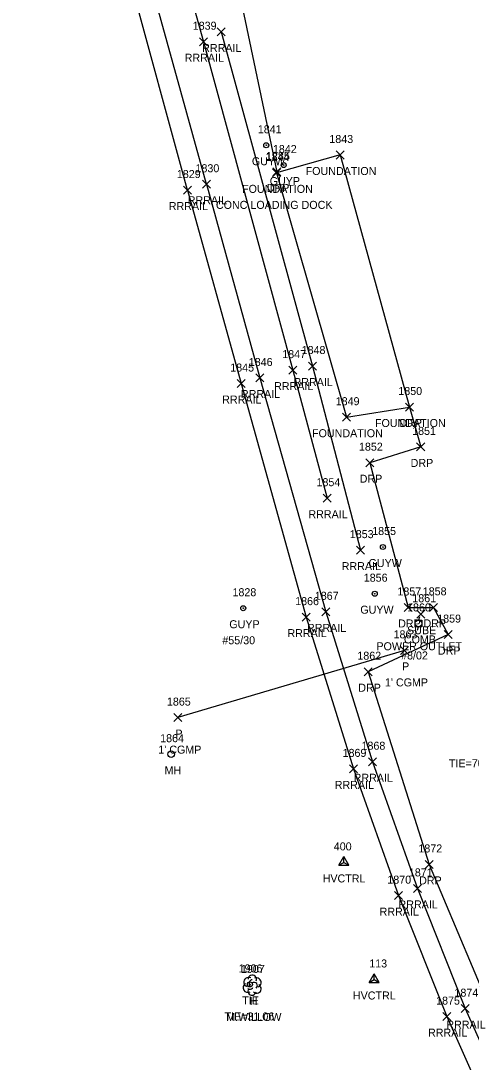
# Model space of a CAD drawing. Extents: x 1635588 to 1637550, y 621583 to 623638.
# Drawn here: x 1636548.9 to 1636661.5, y 622425.2 to 622685.3 of the extents above; entities that cross this region are included whole.
import ezdxf

# ---------------------------------------------------------------- set-up
doc = ezdxf.new("R2010")
doc.units = 0
for name, color, linetype in [('C_A', 7, 'Continuous'), ('C_C', 7, 'Continuous'), ('C_I', 7, 'Continuous'), ('CBP', 7, 'Continuous'), ('CPSM', 7, 'Continuous'), ('D_A', 7, 'Continuous'), ('D_C', 7, 'Continuous'), ('D_I', 7, 'Continuous'), ('D_TIC', 7, 'Continuous'), ('DCP', 7, 'Continuous'), ('L_A', 7, 'Continuous'), ('L_C', 7, 'Continuous'), ('L_I', 7, 'Continuous'), ('L_TIC', 7, 'Continuous'), ('LBC', 7, 'Continuous'), ('LTD', 7, 'Continuous'), ('R_A', 7, 'Continuous'), ('R_I', 7, 'Continuous'), ('R_TIC', 7, 'Continuous'), ('RDP', 7, 'Continuous'), ('RR', 7, 'Continuous'), ('U_A', 7, 'Continuous'), ('U_C', 7, 'Continuous'), ('U_I', 7, 'Continuous'), ('U_TIC', 7, 'Continuous'), ('UP', 7, 'Continuous'), ('UPGW', 7, 'Continuous'), ('UUMH', 7, 'Continuous')]:
    doc.layers.add(name, color=color, linetype=linetype)

msp = doc.modelspace()

# ---------------------------------------------------------------- linework, layer by layer
at = {"layer": 'CBP'}
for radius in [0.625, 0.0833]:
    msp.add_circle((1636606.18, 622444.61), radius, dxfattribs=at)
at = {"layer": 'CPSM'}
for p, q in [((1636628.4, 622474.37), (1636629.65, 622476.53)), ((1636628.4, 622474.37), (1636629.65, 622475.09)), ((1636630.9, 622474.37), (1636629.65, 622476.53)), ((1636629.65, 622475.09), (1636629.65, 622476.53)), ((1636629.65, 622475.09), (1636629.65, 622475.09)), ((1636629.65, 622475.09), (1636630.9, 622474.37)), ((1636628.4, 622474.37), (1636630.9, 622474.37)), ((1636635.97, 622445.12), (1636637.22, 622447.29)), ((1636635.97, 622445.12), (1636637.22, 622445.84)), ((1636638.47, 622445.12), (1636637.22, 622447.29)), ((1636637.22, 622445.84), (1636637.22, 622447.29)), ((1636637.22, 622445.84), (1636637.22, 622445.84)), ((1636637.22, 622445.84), (1636638.47, 622445.12)), ((1636635.97, 622445.12), (1636638.47, 622445.12))]:
    msp.add_line(p, q, dxfattribs=at)
at = {"layer": 'D_TIC'}
for points in [[(1636643.81, 622527.06), (1636645.81, 622529.06)], [(1636645.81, 622527.06), (1636643.81, 622529.06)], [(1636587.18, 622510.26), (1636589.18, 622512.26)], [(1636589.18, 622510.26), (1636587.18, 622512.26)]]:
    msp.add_lwpolyline(points, dxfattribs=at)
at = {"layer": 'DCP'}
msp.add_lwpolyline([(1636644.81, 622528.06), (1636588.18, 622511.26)], dxfattribs=at)
at = {"layer": 'L_TIC'}
for points in [[(1636627.71, 622650.82), (1636629.71, 622652.82)], [(1636629.71, 622650.82), (1636627.71, 622652.82)], [(1636627.71, 622650.82), (1636629.71, 622652.82)], [(1636629.71, 622650.82), (1636627.71, 622652.82)], [(1636611.83, 622646.36), (1636613.83, 622648.36)], [(1636613.83, 622646.36), (1636611.83, 622648.36)], [(1636645.02, 622587.86), (1636647.02, 622589.86)], [(1636647.02, 622587.86), (1636645.02, 622589.86)], [(1636645.02, 622587.86), (1636647.02, 622589.86)], [(1636647.02, 622587.86), (1636645.02, 622589.86)], [(1636629.31, 622585.31), (1636631.31, 622587.31)], [(1636631.31, 622585.31), (1636629.31, 622587.31)]]:
    msp.add_lwpolyline(points, dxfattribs=at)
at = {"layer": 'LBC'}
for points in [[(1636628.71, 622651.82), (1636612.83, 622647.36), (1636630.31, 622586.31), (1636646.02, 622588.86)], [(1636628.71, 622651.82), (1636646.02, 622588.86)]]:
    msp.add_lwpolyline(points, dxfattribs=at)
at = {"layer": 'LTD'}
msp.add_line((1636606.71, 622444.47), (1636606.71, 622444.47), dxfattribs=at)
msp.add_line((1636606.71, 622444.47), (1636606.71, 622444.47), dxfattribs=at)
msp.add_arc((1636606.76, 622445.9), 1.05, 335.5272, 180.9563, dxfattribs=at)
for centre, major_axis, ratio, start_param, end_param in [((1636605.92, 622445.13), (1.21, -0.51), 0.895232, 1.570796, 4.712389), ((1636607.75, 622445.05), (-1.14, -0.48), 0.949671, 1.570796, 4.712389), ((1636605.63, 622443.76), (0.58, -1.04), 0.959034, 3.141593, 6.283185), ((1636606.71, 622442.97), (0.26, 1.06), 0.942809, 1.570796, 4.712389), ((1636606.25, 622443.72), (-0.625, -0.083), 0.423636, 0, 3.141593), ((1636606.5, 622444.93), (-0.208, -0.792), 0.645439, 3.141593, 6.283185), ((1636607.21, 622444.3), (-0.5, 0.667), 0.989748, 3.141593, 6.283185), ((1636607.71, 622443.64), (-1.09, 0.79), 0.841452, 1.570796, 4.712389)]:
    msp.add_ellipse(centre, major_axis=major_axis, ratio=ratio, start_param=start_param, end_param=end_param, dxfattribs=at)
at = {"layer": 'R_TIC'}
for points in [[(1636597.96, 622681.56), (1636599.96, 622683.56)], [(1636599.96, 622681.56), (1636597.96, 622683.56)], [(1636593.59, 622679.12), (1636595.59, 622681.12)], [(1636595.59, 622679.12), (1636593.59, 622681.12)], [(1636611.89, 622646.59), (1636613.89, 622648.59)], [(1636613.89, 622646.59), (1636611.89, 622648.59)], [(1636589.62, 622642.06), (1636591.62, 622644.06)], [(1636591.62, 622642.06), (1636589.62, 622644.06)], [(1636594.36, 622643.51), (1636596.36, 622645.51)], [(1636596.36, 622643.51), (1636594.36, 622645.51)], [(1636620.79, 622598.09), (1636622.79, 622600.09)], [(1636622.79, 622598.09), (1636620.79, 622600.09)], [(1636607.64, 622595.11), (1636609.64, 622597.11)], [(1636609.64, 622595.11), (1636607.64, 622597.11)], [(1636615.94, 622597.07), (1636617.94, 622599.07)], [(1636617.94, 622597.07), (1636615.94, 622599.07)], [(1636602.96, 622593.72), (1636604.96, 622595.72)], [(1636604.96, 622593.72), (1636602.96, 622595.72)], [(1636645.02, 622587.86), (1636647.02, 622589.86)], [(1636647.02, 622587.86), (1636645.02, 622589.86)], [(1636647.84, 622577.89), (1636649.84, 622579.89)], [(1636649.84, 622577.89), (1636647.84, 622579.89)], [(1636635.11, 622573.95), (1636637.11, 622575.95)], [(1636637.11, 622573.95), (1636635.11, 622575.95)], [(1636624.5, 622565.08), (1636626.5, 622567.08)], [(1636626.5, 622565.08), (1636624.5, 622567.08)], [(1636632.82, 622552.1), (1636634.82, 622554.1)], [(1636634.82, 622552.1), (1636632.82, 622554.1)], [(1636644.72, 622537.78), (1636646.72, 622539.78)], [(1636646.72, 622537.78), (1636644.72, 622539.78)], [(1636651.05, 622537.81), (1636653.05, 622539.81)], [(1636653.05, 622537.81), (1636651.05, 622539.81)], [(1636619.27, 622535.36), (1636621.27, 622537.36)], [(1636621.27, 622535.36), (1636619.27, 622537.36)], [(1636624.13, 622536.69), (1636626.13, 622538.69)], [(1636626.13, 622536.69), (1636624.13, 622538.69)], [(1636654.67, 622531), (1636656.67, 622533)], [(1636656.67, 622531), (1636654.67, 622533)], [(1636634.76, 622521.73), (1636636.76, 622523.73)], [(1636636.76, 622521.73), (1636634.76, 622523.73)], [(1636635.8, 622499.24), (1636637.8, 622501.24)], [(1636637.8, 622499.24), (1636635.8, 622501.24)], [(1636631.07, 622497.45), (1636633.07, 622499.45)], [(1636633.07, 622497.45), (1636631.07, 622499.45)], [(1636649.96, 622473.58), (1636651.96, 622475.58)], [(1636651.96, 622473.58), (1636649.96, 622475.58)], [(1636647.02, 622467.59), (1636649.02, 622469.59)], [(1636649.02, 622467.59), (1636647.02, 622469.59)], [(1636642.29, 622465.78), (1636644.29, 622467.78)], [(1636644.29, 622465.78), (1636642.29, 622467.78)], [(1636658.97, 622437.55), (1636660.97, 622439.55)], [(1636660.97, 622437.55), (1636658.97, 622439.55)], [(1636654.39, 622435.56), (1636656.39, 622437.56)], [(1636656.39, 622435.56), (1636654.39, 622437.56)]]:
    msp.add_lwpolyline(points, dxfattribs=at)
at = {"layer": 'RDP'}
for points in [[(1636570.79, 622806.25), (1636586.44, 622757.82), (1636599.97, 622709.22), (1636612.89, 622647.59)], [(1636612.89, 622647.59), (1636612.83, 622647.36)], [(1636646.02, 622588.86), (1636648.84, 622578.89), (1636636.11, 622574.95), (1636645.72, 622538.78), (1636652.05, 622538.81), (1636655.67, 622532), (1636635.76, 622522.73), (1636650.96, 622474.58), (1636665.26, 622440.62), (1636677.8, 622409.87), (1636697.86, 622367.66), (1636712.78, 622335.23), (1636728.36, 622343.83), (1636729.47, 622348.39)]]:
    msp.add_lwpolyline(points, dxfattribs=at)
at = {"layer": 'RR'}
for points in [[(1636548.94, 622846.43), (1636558.8, 622810.29), (1636577.63, 622741.25), (1636594.59, 622680.12), (1636616.94, 622598.07), (1636625.5, 622566.08)], [(1636590.62, 622643.06), (1636576, 622696.58)], [(1636595.36, 622644.51), (1636580.62, 622697.82)], [(1636598.96, 622682.56), (1636621.79, 622599.09), (1636633.82, 622553.1)], [(1636595.36, 622644.51), (1636608.64, 622596.11), (1636625.13, 622537.69), (1636636.8, 622500.24), (1636648.02, 622468.59), (1636659.97, 622438.55), (1636673.52, 622408.34), (1636693.85, 622366.08), (1636714.7, 622324.39), (1636733.88, 622287.48), (1636747.97, 622261.4), (1636765.42, 622232.02), (1636782.99, 622205.69), (1636804, 622177.32), (1636821.45, 622155.32), (1636839.4, 622134.64), (1636866.41, 622104.91), (1636933.01, 622032.15), (1636992.12, 621967.88), (1637026.25, 621930.62), (1637051.37, 621903.17)], [(1636590.62, 622643.06), (1636603.96, 622594.72), (1636620.27, 622536.36), (1636632.07, 622498.45), (1636643.29, 622466.78), (1636655.39, 622436.56), (1636668.93, 622406.09), (1636689.56, 622363.97), (1636710.33, 622322.06), (1636729.55, 622284.99), (1636743.57, 622259.26), (1636761.55, 622228.91), (1636778.55, 622203.2), (1636800.49, 622173.78), (1636817.8, 622151.9), (1636836.04, 622130.9), (1636862.72, 622101.67), (1636929.58, 622028.72), (1636988.41, 621964.46), (1637027.08, 621922.66), (1637047.82, 621899.75)]]:
    msp.add_lwpolyline(points, dxfattribs=at)
at = {"layer": 'U_TIC'}
for points in [[(1636647.92, 622536.09), (1636649.92, 622538.09)], [(1636649.92, 622536.09), (1636647.92, 622538.09)]]:
    msp.add_lwpolyline(points, dxfattribs=at)
at = {"layer": 'UP'}
for p, q in [((1636647.43, 622533.96), (1636647.43, 622535.62)), ((1636647.43, 622535.62), (1636649.1, 622535.62)), ((1636648.52, 622536.46), (1636648.27, 622535.62)), ((1636648.27, 622534.79), (1636648.27, 622534.79)), ((1636649.1, 622535.62), (1636649.1, 622533.96)), ((1636649.1, 622533.96), (1636647.43, 622533.96)), ((1636648.02, 622533.12), (1636648.27, 622533.96))]:
    msp.add_line(p, q, dxfattribs=at)
msp.add_circle((1636648.27, 622534.79), 0.833, dxfattribs=at)
at = {"layer": 'UPGW'}
for centre, radius in [((1636610.27, 622654.26), 0.625), ((1636610.27, 622654.26), 0.0833), ((1636614.61, 622649.31), 0.625), ((1636614.61, 622649.31), 0.0833), ((1636639.42, 622553.88), 0.625), ((1636639.42, 622553.88), 0.0833), ((1636637.36, 622542.22), 0.625), ((1636637.36, 622542.22), 0.0833), ((1636604.51, 622538.59), 0.625), ((1636604.51, 622538.59), 0.0833)]:
    msp.add_circle(centre, radius, dxfattribs=at)
at = {"layer": 'UUMH'}
for p, q in [((1636586.49, 622502.12), (1636586.49, 622502.12)), ((1636587.32, 622502.12), (1636587.32, 622502.12))]:
    msp.add_line(p, q, dxfattribs=at)
msp.add_circle((1636586.49, 622502.12), 0.833, dxfattribs=at)

# ---------------------------------------------------------------- texts
at = {"layer": 'C_A'}
for s, p in [('HVCTRL', (1636624.35, 622470.09)), ('TIE', (1636604.26, 622439.61)), ('HVCTRL', (1636631.91, 622440.84))]:
    msp.add_text(s, height=2, dxfattribs=at).set_placement(p)
at = {"layer": 'C_C'}
for s, p in [('TIE=70.14 CRN BLDG', (1636655.89, 622498.85)), ('TIE=31.06', (1636599.84, 622435.61))]:
    msp.add_text(s, height=2, dxfattribs=at).set_placement(p)
at = {"layer": 'C_I'}
for s, p in [('400', (1636627.13, 622478.09)), ('1906', (1636603.35, 622447.61)), ('113', (1636635.99, 622448.84))]:
    msp.add_text(s, height=2, dxfattribs=at).set_placement(p)
at = {"layer": 'D_A'}
for p in [(1636644.19, 622523.06), (1636587.56, 622506.26)]:
    msp.add_text('P', height=2, dxfattribs=at).set_placement(p)
at = {"layer": 'D_C'}
for p in [(1636639.92, 622519.06), (1636583.29, 622502.26)]:
    msp.add_text("1' CGMP", height=2, dxfattribs=at).set_placement(p)
at = {"layer": 'D_I'}
for s, p in [('1863', (1636642.07, 622531.06)), ('1865', (1636585.44, 622514.26))]:
    msp.add_text(s, height=2, dxfattribs=at).set_placement(p)
at = {"layer": 'L_A'}
for s, p in [('FOUNDATION', (1636620.1, 622646.82)), ('FOUNDATION', (1636620.1, 622646.82)), ('FOUNDATION', (1636604.22, 622642.36)), ('FOUNDATION', (1636637.42, 622583.86)), ('FOUNDATION', (1636637.42, 622583.86)), ('FOUNDATION', (1636621.7, 622581.31)), ('H', (1636606.15, 622439.47))]:
    msp.add_text(s, height=2, dxfattribs=at).set_placement(p)
at = {"layer": 'L_C'}
for s, p in [('CONC LOADING DOCK', (1636597.68, 622638.36)), ('M.WILLOW', (1636600.24, 622435.47))]:
    msp.add_text(s, height=2, dxfattribs=at).set_placement(p)
at = {"layer": 'L_I'}
for s, p in [('1843', (1636626.02, 622654.82)), ('1843', (1636626.02, 622654.82)), ('1844', (1636610.13, 622650.36)), ('1850', (1636643.25, 622591.86)), ('1850', (1636643.25, 622591.86)), ('1849', (1636627.61, 622589.31)), ('1907', (1636603.94, 622447.47))]:
    msp.add_text(s, height=2, dxfattribs=at).set_placement(p)
at = {"layer": 'R_A'}
for s, p in [('RRRAIL', (1636594.25, 622677.56)), ('RRRAIL', (1636589.88, 622675.12)), ('DRP', (1636610.38, 622642.59)), ('RRRAIL', (1636590.65, 622639.51)), ('RRRAIL', (1636585.91, 622638.06)), ('RRRAIL', (1636612.23, 622593.07)), ('RRRAIL', (1636617.08, 622594.09)), ('RRRAIL', (1636599.25, 622589.72)), ('RRRAIL', (1636603.93, 622591.11)), ('DRP', (1636643.51, 622583.86)), ('DRP', (1636646.33, 622573.89)), ('DRP', (1636633.6, 622569.95)), ('RRRAIL', (1636620.79, 622561.08)), ('RRRAIL', (1636629.11, 622548.1)), ('RRRAIL', (1636620.43, 622532.69)), ('DRP', (1636643.21, 622533.78)), ('DRP', (1636649.54, 622533.81)), ('RRRAIL', (1636615.56, 622531.36)), ('DRP', (1636653.15, 622527)), ('DRP', (1636633.25, 622517.73)), ('RRRAIL', (1636627.37, 622493.45)), ('RRRAIL', (1636632.09, 622495.24)), ('DRP', (1636648.45, 622469.58)), ('RRRAIL', (1636643.31, 622463.59)), ('RRRAIL', (1636638.58, 622461.78)), ('RRRAIL', (1636655.26, 622433.55)), ('RRRAIL', (1636650.68, 622431.56))]:
    msp.add_text(s, height=2, dxfattribs=at).set_placement(p)
at = {"layer": 'R_I'}
for s, p in [('1839', (1636591.89, 622683.12)), ('1285', (1636610.2, 622650.59)), ('1830', (1636592.58, 622647.51)), ('1829', (1636587.92, 622646.06)), ('1847', (1636614.25, 622601.07)), ('1848', (1636619.1, 622602.09)), ('1845', (1636601.26, 622597.72)), ('1846', (1636605.89, 622599.11)), ('1850', (1636643.25, 622591.86)), ('1851', (1636646.71, 622581.89)), ('1852', (1636633.42, 622577.95)), ('1854', (1636622.81, 622569.08)), ('1853', (1636631.13, 622556.1)), ('1867', (1636622.39, 622540.69)), ('1857', (1636643.03, 622541.78)), ('1858', (1636649.36, 622541.81)), ('1866', (1636617.48, 622539.36)), ('1859', (1636652.97, 622535)), ('1862', (1636633.02, 622525.73)), ('1869', (1636629.33, 622501.45)), ('1868', (1636634.06, 622503.24)), ('1872', (1636648.27, 622477.58)), ('1871', (1636645.89, 622471.59)), ('1870', (1636640.51, 622469.78)), ('1874', (1636657.28, 622441.55)), ('1875', (1636652.7, 622439.56))]:
    msp.add_text(s, height=2, dxfattribs=at).set_placement(p)
at = {"layer": 'U_A'}
for s, p in [('GUYW', (1636606.67, 622649.26)), ('GUYP', (1636611.12, 622644.31)), ('GUYW', (1636635.82, 622548.88)), ('GUYW', (1636633.76, 622537.22)), ('GUYP', (1636601.02, 622533.59)), ('COMB', (1636644.65, 622529.79)), ('SUBE', (1636645.45, 622532.09)), ('MH', (1636584.85, 622497.12))]:
    msp.add_text(s, height=2, dxfattribs=at).set_placement(p)
at = {"layer": 'U_C'}
for s, p in [('#55/30', (1636599.29, 622529.59)), ('POWER OUTLET', (1636637.78, 622528.09)), ('#8/02', (1636643.95, 622525.79))]:
    msp.add_text(s, height=2, dxfattribs=at).set_placement(p)
at = {"layer": 'U_I'}
for s, p in [('1841', (1636608.15, 622657.26)), ('1842', (1636611.92, 622652.31)), ('1855', (1636636.73, 622556.88)), ('1856', (1636634.62, 622545.22)), ('1828', (1636601.82, 622541.59)), ('1861', (1636646.75, 622540.09)), ('1860', (1636645.44, 622537.79)), ('1864', (1636583.75, 622505.12))]:
    msp.add_text(s, height=2, dxfattribs=at).set_placement(p)

doc.saveas('drawing.dxf')
